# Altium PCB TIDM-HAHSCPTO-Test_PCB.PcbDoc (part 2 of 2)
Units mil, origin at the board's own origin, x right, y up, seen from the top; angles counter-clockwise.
Board outline 6700 x 4350 mil, 2 copper layers (Top Layer, Bottom Layer), stack 62 mil thick; 37 components, 162 nets, 491 pads, 55 vias.
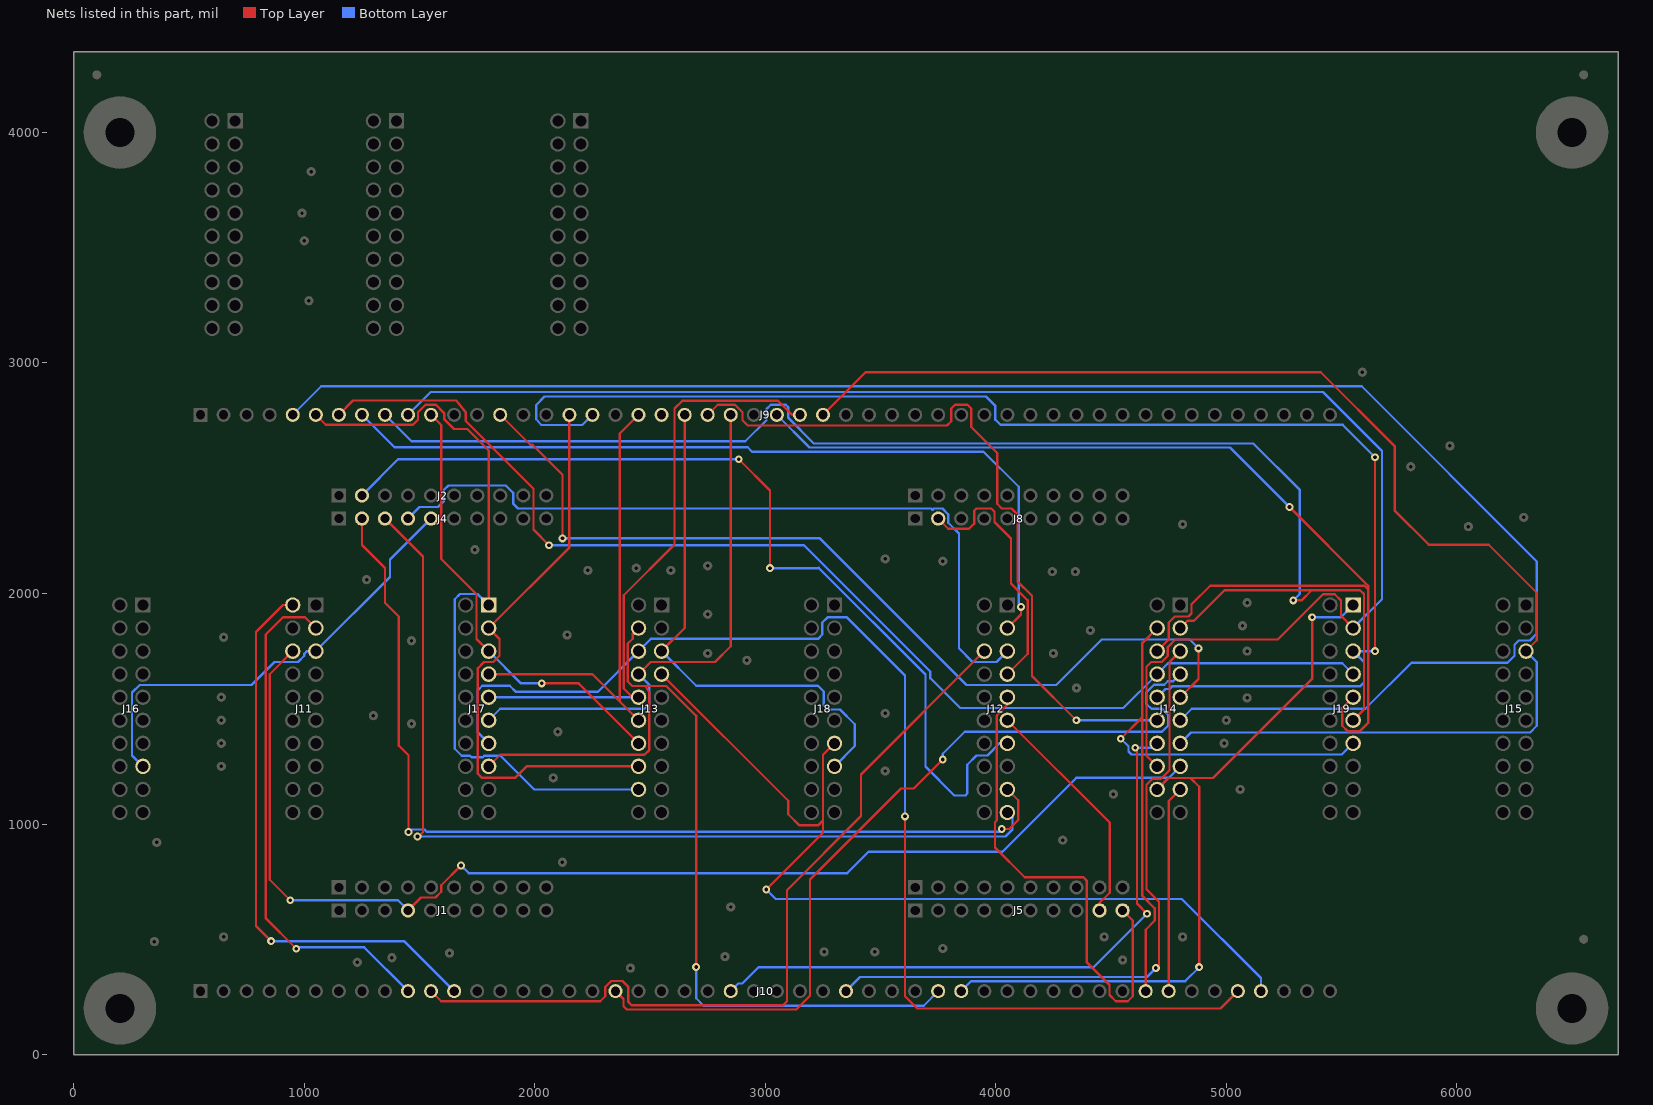
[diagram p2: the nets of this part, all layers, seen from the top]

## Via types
v1: diameter 34, hole 16, Top Layer to Bottom Layer, 55 vias

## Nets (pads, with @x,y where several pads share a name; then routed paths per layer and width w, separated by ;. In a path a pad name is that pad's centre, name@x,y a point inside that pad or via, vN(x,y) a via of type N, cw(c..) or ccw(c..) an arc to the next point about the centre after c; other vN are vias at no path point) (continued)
N2HET1_13/SCI3TX/N2HET2_20/EPWM5B: J1.4 J11.6 J14.15 | length 5341.1
  Top Layer w10: v1(939,669) 850.04,757.96 850.04,1650.04 J11.6@950,1750 ; J1.4@1450,625 1506,681 1569,681 1594,706 1594,734 v1(1680,820)
  Bottom Layer w10: v1(939,669) 1406,669 J1.4@1450,625 ; v1(1680,820) 1713,787 3355,787 3448,880 4029,880 4349,1200 4750,1200 J14.15@4800,1250
N2HET1_14: J4.5 J11.5 J16.15 | length 1997.8
  Bottom Layer w10: J16.15@300,1250 253,1297 253,1570 286,1603 771,1603 871,1703 973,1703 1000,1730 1000,1738 1012,1750 J11.5@1050,1750 1371.84,2071.84 1371.84,2146.84 J4.5@1550,2325
N2HET1_16/EPWM1SYNCI/EPWM1SYNCO: J4.3 J12.19 | length 4150.2
  Top Layer w10: J4.3@1350,2325 1515,2160 1515,964 1497,946 v1(1491,946)
  Bottom Layer w10: v1(1491,946) 4042,946 4072,976 4072,1050 J12.19@4050,1050
N2HET1_18/EMIF_RNW/EPWM6A: J4.2 J12.17 | length 4270.5
  Top Layer w10: J4.2@1250,2325 1250,2210 1350,2110 1350,1960 1410,1900 1410,1340 1452,1298 v1(1452,965) ; v1(4026,978) 4058,978 4097,1017 4097,1103 J12.17@4050,1150
  Bottom Layer w10: v1(1452,965) 1462.87,975.87 1521.05,975.87 1530.49,966.44 4014.44,966.44 v1(4026,978)
N2HET1_21/EMIF_NDQM_2: J10.24 J14.14 | length 2789.2
  Top Layer w10: v1(4605,1331) 4612,1324 4612,655 v1(4656,611)
  Bottom Layer w10: J10.24@2850,275 2883,308 2900,308 2971,379 4424,379 v1(4656,611) ; v1(4605,1331) 4681,1331 J14.14@4700,1350
N2HET1_22/EMIF_NDQM_3: J2.2 J12.13 | length 4067.6
  Top Layer w10: v1(2885,2582) 3020,2447 v1(3020,2110)
  Bottom Layer w10: J2.2@1250,2425 1407,2582 v1(2885,2582) ; v1(3020,2110) 3230.68,2110 3231.68,2111 3694.46,1648.22 3694.46,1249.54 3820,1124 3868,1124 3876,1132 3876,1257 3916,1297 3963.34,1297 4016.34,1350 J12.13@4050,1350
N2HET1_23/EMIF_BA_0: J10.12 J11.2 | length 2459.5
  Top Layer w10: v1(856,492) 790.76,557.24 790.76,1832.76 908,1950 J11.2@950,1950
  Bottom Layer w10: v1(856,492) 1433,492 J10.12@1650,275
N2HET1_24/MIBSPI1NCS_5/MII_RXD_0/RMII_RXD_0: J5.9 J12.11 | length 1027
  Top Layer w10: J12.11@4050,1450 4493.87,1006.13 4493.87,701.87 4450,658 J5.9@4450,625
N2HET1_26/MII_RXD_1/RMII_RXD_1: J5.10 J12.9 | length 2180.8
  Top Layer w10: J12.9@4050,1550 4050,1517 4003.66,1470.66 4003.66,1015.41 3996.13,1007.87 3996.13,897.87 4125,769 4380,769 4393.87,755.13 4393.87,401.13 4493.39,301.61 4493.39,258 4520.39,231 4572,231 4594,253 4594,581 J5.10@4550,625
N2HET1_27: J9.8 J12.3 | length 3619.8
  Top Layer w10: J12.3@4050,1850 4109,1909 v1(4109,1942)
  Bottom Layer w10: J9.8@1250,2775 1391,2634 2923.56,2634 2942.44,2615.13 3946.87,2615.13 4099,2463 4099,1952 v1(4109,1942)
N2HET1_28/MII_RXCLK/RMII_REFCLK/MII_RX_AVCLK4: J8.2 J12.7 | length 1139.1
  Top Layer w10: J8.2@3750,2325 3794,2281 3884,2281 3906.13,2303.13 3906.13,2359.13 3916,2369 3980,2369 3994,2355 3994,2310 4066,2238 4066,2042.87 4138.87,1970 4138.87,1738.87 J12.7@4050,1650
N2HET1_29: J10.11 J12.6 | length 3585
  Top Layer w10: J10.11@1550,275 1594,231 2284,231 2306,253 2306,293 2332,319 2380,319 2406,293 2406,228 2420.87,213.13 3076.13,213.13 3094,231 3094,713 3415.25,1034.25 3415.25,1215.25 J12.6@3950,1750
N2HET1_30/MII_RX_DV/EQEP2S: J4.4 J12.5 | length 3370.5
  Bottom Layer w10: J4.4@1450,2325 1500,2375 1580,2375 1606.13,2401.13 1606.13,2450 1625,2468.87 1874.13,2468.87 1906,2437 1906,2390 1927.13,2368.87 3718.8,2368.87 3724.42,2363.25 3726.2,2363.25 3731.83,2368.87 3768.17,2368.87 3793.87,2343.17 3793.87,2306.83 3840,2260.7 3840,1762 3899,1703 4003,1703 J12.5@4050,1750
N2HET1_31: J10.10 J11.3 | length 2251.8
  Top Layer w10: v1(965,459) 832.16,591.84 832.16,1821.16 908,1897 1003,1897 J11.3@1050,1850
  Bottom Layer w10: v1(965,459) 970.7,464.7 1260.3,464.7 J10.10@1450,275
N2HET2_0: J9.5 J14.11 | length 7807
  Bottom Layer w10: J9.5@950,2775 1074,2899 5587,2899 6347,2139 6347,1826 6317.34,1796.34 6268.34,1796.34 6250,1778 6250,1730 6220,1700 5803,1700 5603,1500 4850,1500 J14.11@4800,1450
N2HET2_1/N2HET1_NDIS: J9.6 J13.18 J17.1 | length 3291.5
  Top Layer w10: J9.6@1050,2775 1093.39,2731.61 1471,2731.61 1493.39,2754 1493.39,2786 1526.39,2819 1571,2819 1606.61,2783.39 1606.61,2757.03 1649.9,2713.74 1706.61,2713.74 1800,2620.35 J17.1@1800,1950
  Bottom Layer w10: J17.1@1800,1950 1752,1998 1676,1998 1653,1975 1653,1326 1682.66,1296.34 1719.19,1296.34 1725.53,1290 1774.47,1290 1780.81,1296.34 1851.61,1296.34 1997.95,1150 J13.18@2450,1150
N2HET2_2/N2HET2_NDIS: J9.18 J14.10 J19.5 | length 6148
  Top Layer w10: v1(5645,1750) v1(5645,2591)
  Bottom Layer w10: J9.18@2250,2775 2206,2731 2028,2731 2006,2756.25 2006,2818 2042.13,2854.13 3956.87,2854.13 3998,2813 3998,2754 4020.39,2731.61 5504.39,2731.61 v1(5645,2591) ; J14.10@4700,1550 4735.79,1585.79 4753,1585.79 4764.21,1597 5580,1597 5597,1614 5597,1703 J19.5@5550,1750 v1(5645,1750)
N2HET2_3/MIBSPI2CLK: J9.17 J13.16 J17.3 | length 2509
  Top Layer w10: J9.17@2150,2775 2150,2200 J17.3@1800,1850 1847,1803 1847,1730 1820,1703 1780,1703 1753,1676 1753,1218 1771,1200 1914,1200 1964,1250 J13.16@2450,1250
N2HET2_4: J9.14 J14.9 | length 4018.2
  Top Layer w10: J9.14@1850,2775 1980,2645 1990,2645 2120,2515 v1(2120,2239) ; J14.9@4800,1550 4879,1629 v1(4879,1762)
  Bottom Layer w10: v1(2120,2239) 3236.89,2239 3872.89,1603 4262,1603 4459,1800 4841,1800 v1(4879,1762)
N2HET2_5: J9.11 J13.14 J17.5 | length 1944.2
  Top Layer w10: J9.11@1550,2775 1593.87,2731.13 1593.87,2150.13 1747,1997 1747,1803 J17.5@1800,1750 ; v1(2030,1610) 2190,1610 2197,1603 J13.14@2450,1350
  Bottom Layer w10: J17.5@1800,1750 1940,1610 v1(2030,1610)
N2HET2_6: J9.7 J14.8 J19.7 | length 5224.5
  Top Layer w10: J9.7@1150,2775 1211.87,2836.87 1660,2836.87 1700,2787.39 1700,2748 1994,2454 1994,2277 v1(2061.87,2209.13)
  Bottom Layer w10: v1(2061.87,2209.13) 3167.5,2209.13 3716.14,1660.48 3716.14,1632 3845.15,1503 4553,1503 J14.8@4700,1650 4747,1697 5503,1697 J19.7@5550,1650
N2HET2_7/MIBSPI2NCS_0: J9.20 J13.12 J17.7 | length 2009.8
  Top Layer w10: J17.7@1800,1650 2250,1650 2367.91,1532.09 ; J13.12@2450,1450 2367.91,1532.09 ; J9.20@2450,2775 2367.91,2692.91 2367.91,1532.09
N2HET2_8: J10.19 J14.7 | length 3657.6
  Top Layer w10: J10.19@2350,275 2384.77,240.23 2384.77,209.77 2399.28,195.25 3134.25,195.25 3194,255 3194,759 3589,1154 3644,1154 v1(3770,1280)
  Bottom Layer w10: v1(3770,1280) 3770,1305 3865,1400 4721,1400 4747,1426 4747,1474 4721,1500 4675,1500 4653,1522 4653,1570 4686.66,1603.66 4730.66,1603.66 4746,1619 4769,1619 J14.7@4800,1650
N2HET2_9: J9.27 J13.10 J17.9 | length 2618.6
  Top Layer w10: J13.10@2450,1550 2424,1550 2385.79,1588.21 2385.79,1992.13 2606,2212.34 2606,2802 2640.26,2836.26 3054.74,2836.26 3116,2775 J9.27@3150,2775
  Bottom Layer w10: J17.9@1800,1550 J13.10@2450,1550
N2HET2_10: J9.26 J14.6 J19.9 | length 4853.5
  Top Layer w10: J14.6@4700,1750 4750,1800 4750,1874 4776,1900 4836,1900 4849,1913 4849,1953 4930,2034 5599,2034 5615,2018 ; v1(5274,2375) 5615,2034 5615,2018 ; J19.9@5550,1550 5503,1503 5503,1426 5526,1403 5580,1403 5615,1438 5615,2018
  Bottom Layer w10: J9.26@3050,2775 3192,2633 5016,2633 v1(5274,2375)
N2HET2_11: J9.24 J13.8 J17.11 | length 2329
  Top Layer w10: J13.8@2450,1650 2503,1703 2782,1703 2850,1771 J9.24@2850,2775
  Bottom Layer w10: J17.11@1800,1450 1850,1500 2476,1500 2497,1521 2497,1603 J13.8@2450,1650
N2HET2_12/MIBSPI2NENA/MIBSPI2NCS_1: J10.47 J13.7 J18.13 | length 4133.3
  Top Layer w10: J13.7@2550,1650 3099.53,1100.47 3099.53,1042.33 3147.86,994 3228,994 3250,1016 ; v1(3004,716) 3250,962 3250,1016 ; J18.13@3300,1350 3250,1300 3250,1016
  Bottom Layer w10: v1(3004,716) 3045,675 4806.62,675 5150,331.62 J10.47@5150,275
N2HET2_13/MIBSPI2SOMI: J10.46 J13.6 J17.13 | length 5279.6
  Top Layer w10: v1(3606,1033) 3606,253 3659,200 4975,200 J10.46@5050,275
  Bottom Layer w10: J17.13@1800,1350 1753,1397 1753,1581 1772,1600 1891.25,1600 1918.13,1573.13 2273.13,1573.13 J13.6@2450,1750 2503,1803 3228,1803 3247,1822 3247,1874 3269.34,1896.34 3354,1896.34 3606,1644.34 v1(3606,1033)
N2HET2_14/MIBSPI2SIMO: J9.22 J13.5 J18.15 | length 2289.9
  Top Layer w10: J13.5@2550,1750 2650,1850 J9.22@2650,2775
  Bottom Layer w10: J13.5@2550,1750 2700,1600 3228,1600 3253.66,1574.34 3253.66,1515.34 3272,1497 3324,1497 3388.21,1432.79 3388.21,1338.21 J18.15@3300,1250
N2HET2_15: J10.33 J13.4 J17.15 | length 3932.3
  Top Layer w10: J17.15@1800,1250 1850,1300 2476,1300 2497,1321 2497,1570 2480,1598.66 ; J13.4@2450,1850 2424.88,1824.88 2424.88,1803.66 2403.66,1782.44 2403.66,1618 2423,1598.66 2468.34,1598.66 2570.34,1598.66 2700,1469 v1(2700,380)
  Bottom Layer w10: v1(2700,380) 2700,244 2732,212 3687,212 J10.33@3750,275
N2HET2_16: J10.29 J14.5 | length 2870.4
  Top Layer w10: v1(4694.37,375.37) 4707.75,388.75 4707.75,662.75 4653.66,716.84 4653.66,1170 4680,1196.34 4716.34,1196.34 4753,1233 4753,1703 J14.5@4800,1750
  Bottom Layer w10: J10.29@3350,275 3411.26,336.26 4655.26,336.26 v1(4694.37,375.37)
N2HET2_17: J10.34 J14.18 J19.1 | length 3249.4
  Top Layer w10: J14.18@4700,1150 4749.19,1199.19 4844,1199.19 ; v1(4882,379) 4882,1161.19 4844,1199.19 ; v1(5372,1897) 5372,1629 4942.19,1199.19 4844,1199.19
  Bottom Layer w10: J10.34@3850,275 3893.39,318.39 4821.39,318.39 v1(4882,379) ; v1(5372,1897) 5497,1897 J19.1@5550,1950
N2HET2_18: J10.43 J14.17 | length 895.7
  Top Layer w10: J10.43@4750,275 4750,1100 J14.17@4800,1150
N2HET2_19/LIN2RX: J9.10 J14.16 J19.3 | length 6791.7
  Top Layer w10: J14.16@4700,1250 4653.66,1296.34 4653.66,1682 4674.66,1703 4719.34,1703 4746.34,1730 4746.34,1768 4778.34,1800 5223,1800 5419.34,1996.34 5470.66,1996.34 5497,1970 5497,1903 J19.3@5550,1850
  Bottom Layer w10: J9.10@1450,2775 1549,2874 5419,2874 5675,2618 5675,1975 J19.3@5550,1850
N2HET2_20/LIN2TX: J9.9 J14.3 J19.11 | length 6318.1
  Top Layer w10: J14.3@4800,1850 4831.78,1881.78 4859.3,1881.78 4991.73,2014.21 5370,2014.21 ; v1(5290,1970) 5325.79,1970 5370,2014.21 ; J19.11@5550,1450 5597,1497 5597,1997.21 5580,2014.21 5370,2014.21
  Bottom Layer w10: J9.9@1350,2775 1465,2660 2913,2660 3005,2752 3005,2800 3023.39,2818.39 3088.61,2818.39 3100,2807 3100,2761.41 3210.54,2650.87 5117.13,2650.87 5319,2449 5319,1999 v1(5290,1970)
N2HET2_21: J10.42 J14.4 J19.13 | length 2855.8
  Top Layer w10: v1(4542.12,1370.13) 4632,1460 4635.79,1460 ; J10.42@4650,275 4650,541.13 4689.87,581 4689.87,634 4635.79,688.09 4635.79,1460 ; J14.4@4700,1850 4635.79,1785.79 4635.79,1460
  Bottom Layer w10: v1@4530,1370 v1@4540,1380 ; v1(4542.12,1370.13) 4575.13,1337.12 4575.13,1313.97 4588,1301.1 5501.1,1301.1 J19.13@5550,1350
N2HET2_22: J9.28 J14.13 J15.5 | length 5928.5
  Top Layer w10: J9.28@3250,2775 3435,2960 5410,2960 5730,2640 5730,2360 5878.69,2211.32 6138.69,2211.32 6347,2003 6347,1797 J15.5@6300,1750
  Bottom Layer w10: J14.13@4800,1350 4847,1397 6318,1397 6347,1426 6347,1703 J15.5@6300,1750
N2HET2_23: J9.23 J14.12 | length 3210.2
  Top Layer w10: J9.23@2750,2775 2793.39,2818.39 2868.61,2818.39 2901,2786 2901,2752 2924,2729 3788,2729 3806.61,2747.61 3806.61,2802 3823,2818.39 3877,2818.39 3893.39,2802 3893.39,2722 4006,2609.39 4006,2389 4026,2369 4068.05,2369 4094.04,2343.01 4094.04,2052.46 4156.75,1989.75 4156.75,1642.47 v1(4349.21,1450)
  Bottom Layer w10: v1(4349.21,1450) J14.12@4700,1450
NERROR: J9.21
pads on no net: FID1.1 FID2.1 FID3.1 H1.1 H2.1 H3.1 H4.1 J3.9 J3.10 J7.9 J7.10 J10.8 J10.9 J10.48 J10.49 J10.50 J11.1 J11.4 J11.8 J12.1 J12.4 J12.15 J13.1 J13.2 J13.3 J14.1 J14.2 J15.7 J15.9 J15.11 J15.13 J15.15 J15.17 J15.19 J16.17 J16.19 J17.17 J17.19 J18.17 J18.19 J19.15 J19.17 J19.19 J20.1 J20.2 J20.3 J21.17 J21.19 J22.17 J22.19

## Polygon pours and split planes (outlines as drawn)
GND on Bottom Layer "BOTTOM_LAYER_GND_P002" (solid, remove dead copper, pour order 2): 101.17,399.51 401.17,399.51 401.17,99.51 6301.17,99.51 6301.17,399.51 6601.17,399.51 6601.17,3799.51 6301.17,3799.51 6301.17,4199.51 401.17,4199.51 401.17,3799.51 101.17,3799.51
GND on Top Layer "TOP_LAYER_GND_P000" (solid, remove dead copper, pour order 0): 100,400 400,400 400,100 6300,100 6300,400 6600,400 6600,3800 6300,3800 6300,4200 400,4200 400,3800 100,3800

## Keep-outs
Keep-Out Layer:
  text ".Layer_Name" at 577,-858.49 h60

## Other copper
Top Layer:
  text ".Layer_Name" at 577,-858.49 h60
Bottom Layer:
  text ".Layer_Name" at 577,-858.49 h60

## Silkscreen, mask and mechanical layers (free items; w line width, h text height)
Top Overlay:
  region: 6200,3590 5900,3590 5900,3490 6200,3490
  text "'.PRJ_Number'.PCB_Rev-" at 4970,3500 h108.27
  text ".Layer_Name" at 577,-858.49 h60
Bottom Overlay:
  text ".Layer_Name" at 577,-858.49 h60
Top Paste:
  text ".Layer_Name" at 577,-858.49 h60
Bottom Paste:
  text ".Layer_Name" at 577,-858.49 h60
Top Solder:
  text ".Layer_Name" at 577,-858.49 h60
  text ".Layer_Name" at 577,-858.49 h60
Bottom Solder:
  text ".Layer_Name" at 577,-858.49 h60
Drill Guide:
  text ".Layer_Name" at 577,-858.49 h60
M1 Board Outline:
  the board outline again, w10
  text ".Layer_Name" at 577,-858.49 h60
M2 Board Dimensions:
  rectangle: 0,-275 125,-150
  rectangle: 125,-400 500,-275
  lines w7: 0,-275 1000,-275 ; 125,-400 125,-150 ; 250,-400 250,-150 ; 500,-400 500,-150 ; 750,-400 750,-150 ; 0,-400 1000,-400 1000,-150 0,-150 0,-400
  text ".Layer_Name" at 577,-858.49 h60
M3 3D STEP Top:
  text ".Layer_Name" at 577,-858.49 h60
M4 3D STEP Bottom:
  text ".Layer_Name" at 577,-858.49 h60
M5 Assembly Top:
  lines w10: -292,-930.17 6308,-930.17 ; -292,-726.83 6310,-726.83 ; -292,-523.5 -292,-1133.5 3713,-1133.5 6310,-1133.5 6310,-523.5 -291.5,-523.5 -291.5,-1133.5 1284,-1133.5 ; 2173,-1133.5 2173,-523.5 ; 3440,-726.83 3440,-523.5 ; 4280,-726.83 4280,-523.5 ; 4902,-1140 4902,-937.17
  text "COMPONENTS MARKED 'DNP' SHOULD NOT BE POPULATED." at 1153.5,-318.5 h60
  text "ASSEMBLY VARIANT:" at 1153,-434 h60
  text ".VariantName" at 2189,-434 h60
  text "PCB VIEWED FROM TOP SIDE" at -228.5,-655.67 h60
  text "BOARD #:" at 2248,-655.67 h60
  text ".PRJ_Number" at 2793.5,-655.67 h60
  text "REV:" at 3638,-655.67 h60
  text ".PCB_Rev" at 3929.5,-655.67 h60
  text "SVN REV:" at 4476,-655.67 h60
  text ".VersionControl_RevNumber" at 4982,-655.67 h60
  text "TID #:" at 2248,-859 h60
  text ".TID" at 2793.5,-859 h60
  text "PLOT NAME =" at -228.5,-1064.34 h60
  text ".plot_File_Name" at 577,-1064.34 h60
  text "GENERATED    :" at 2250,-1064.34 h60
  text ".Print_Date" at 3119.5,-1064.34 h60
  text ".Print_Time" at 3848.5,-1064.34 h60
  text "TEXAS INSTRUMENTS" at 5113,-1064.34 h60
M6 Assembly Bottom:
  lines w10: -292.5,-727.33 6309.5,-727.33 ; -290.5,-930.67 6309.5,-930.67 ; 1115.5,-1140.5 1115.5,-937.67 ; 1737.5,-727.33 1737.5,-524 ; 2577.5,-727.33 2577.5,-524 ; 3844.5,-1134 3844.5,-524 ; 4733.5,-1134 6309,-1134 6309,-524 -292.5,-524 -292.5,-1134 2304.5,-1134 6309.5,-1134 6309.5,-524
  text "COMPONENTS MARKED 'DNP' SHOULD NOT BE POPULATED." at 6102,-318 h60
  text ".VariantName" at 5058,-434 h60
  text "ASSEMBLY VARIANT:" at 6097,-434 h60
  text ".VersionControl_RevNumber" at 1035.5,-656.17 h60
  text "SVN REV:" at 1541.5,-656.17 h60
  text ".PCB_Rev" at 2088,-656.17 h60
  text "REV:" at 2379.5,-656.17 h60
  text ".PRJ_Number" at 3224,-656.17 h60
  text "BOARD #:" at 3769.5,-656.17 h60
  text "PCB VIEWED FROM BOTTOM SIDE" at 6246,-656.17 h60
  text ".TID" at 3224,-859.5 h60
  text "TID #:" at 3769.5,-859.5 h60
  text "TEXAS INSTRUMENTS" at 904.5,-1064.84 h60
  text ".Print_Time" at 2169,-1064.84 h60
  text ".Print_Date" at 2898,-1064.84 h60
  text "GENERATED    :" at 3767.5,-1064.84 h60
  text ".plot_File_Name" at 5440.5,-1064.84 h60
  text "PLOT NAME =" at 6246,-1064.84 h60
M9 Title Sheet:
  drawing of 57 lines, arcs and shapes, not listed
  text "1" at 739.84,8036.5 h70
  text "2" at 3235.5,8036.5 h70
  text "3" at 5724.84,8036.5 h70
  text "4" at 8231.51,8036.5 h70
  text "5" at 10730.5,8036.5 h70
  text "6" at 13235.5,8036.5 h70
  text "A" at -416.5,6893.5 h70
  text "A" at 14383.5,6893.5 h70
  text "B" at -416.5,4513.5 h70
  text "B" at 14383.5,4513.5 h70
  text "C" at -416.5,2138.5 h70
  text "C" at 14383.5,2138.5 h70
  text "PROJECT TITLE:" at 11343.5,277.5 h45
  text ".PRJ_Title" at 11393.5,144.17 h70
  text "DESIGNED FOR:" at 11343.5,-23.5 h45
  text ".PRJ_Customer" at 11393.5,-163.5 h70
  text "D" at -416.5,-231.5 h70
  text "D" at 14383.5,-231.5 h70
  text "FILE NAME:" at 11343.5,-323.5 h45
  text ".PCB_File_Name_No_Path" at 11393.5,-443.5 h70
  text "Texas Instruments (TI) and/or its licensors do not warrant the accuracy or completeness of this specification" at 6374,-605.34 h45
  text "ENGINEER:" at 11343.5,-613.5 h45
  text "LAYOUT BY:" at 12848.5,-613.5 h45
  text "or any information contained therein. TI and/or its licensors do not warrant that this design will meet" at 6329.01,-718 h45
  text ".PRJ_Engineer" at 11393.5,-768.49 h70
  text ".PCB_Layout" at 12899,-768.49 h70
  text "the specifications, will be suitable for your application or fit for any particular purpose, or will operate in" at 6329.01,-830.67 h45
  text ".Layer_Name" at 577,-858.49 h60
  text "ALTIUM DESIGNER VERSION:" at 12848.5,-923.5 h45
  text "an implementation. TI and/or its licensors do not warrant that the design is production worthy. You should" at 6329.01,-943.33 h45
  text "completely validate and test your design implementation to confirm the system functionality for your application." at 6374,-1056 h45
  text ".print_Scale" at 11393.5,-1056.83 h70
  text ".Application_BuildNumber" at 12899,-1056.83 h70
  text "1" at 739.84,-1263.5 h70
  text "2" at 3235.5,-1263.5 h70
  text "3" at 5724.84,-1263.5 h70
  text "4" at 8231.51,-1263.5 h70
  text "5" at 10730.5,-1263.5 h70
  text "6" at 13235.5,-1263.5 h70
M10 Fab Notes:
  drawing of 173 lines, arcs and shapes, not listed
  text "DESIGN INFORMATION" at 12378.02,6201 h60
  text "MIN. TRACK WIDTH:" at 11733.46,6021 h60
  text "8" at 12829.7,6021 h60
  text "MIL" at 12984.46,6021 h60
  text "MIN. CLEARANCE:" at 11733.46,5889 h60
  text "0.2" at 12769.7,5889 h60
  text "mm" at 12984.46,5889 h60
  text "MIN. VIA PAD SIZE:" at 11733.46,5757 h60
  text "24" at 12799.71,5757 h60
  text "MIL" at 12984.46,5757 h60
  text "0.05mm (2MIL)" at 12428.46,5615.29 h60
  text "MINIMUM ANNULAR RING" at 11404.23,5611 h60
  text "EXTERNAL" at 13136.46,5611 h60
  text "PER" at 11604.23,5493 h60
  text "IPC-D-275 CLASS 2 LEVEL C" at 11824.23,5493 h60
  text "MIL, HOLES" at 13312.46,5380.71 h60
  text "+/-" at 12920,5380 h60
  text "+/-" at 13774,5380 h60
  text "REGISTRATION TOLERANCES:" at 11404.23,5375 h60
  text "METAL" at 12604,5375 h60
  text "5" at 13180.2,5375 h60
  text "3" at 14013.2,5375 h60
  text "MIL" at 14129.46,5375 h60
  text "+/-" at 13774,5262 h60
  text "HOLE SIZE TOLERANCE (UNLESS OTHERWISE SPECIFIED):" at 11404.23,5257 h60
  text "3" at 14013.2,5257 h60
  text "MIL" at 14129.46,5257 h60
  text "MATERIAL:" at 11329.46,5047.54 h60
  text "FR-4 High Tg" at 12315.9,4907.21 h60
  text "FR-408" at 11750.46,4898.64 h60
  text "OTHER" at 13238.46,4898.64 h60
  text "X" at 12161,4895 h60
  text "62 MIL (1.6mm) +/-10%" at 12070.56,4735.92 h60
  text "THICKNESS:" at 11404.23,4731.64 h60
  text "X" at 11942.4,4731.64 h60
  text "OTHER" at 13355.46,4731.64 h60
  text "TOLERANCE:" at 11404.23,4573.64 h60
  text "X" at 12243.53,4573.64 h60
  text "ANSI IPC-6012 TYPE 3 CLASS 2" at 12430.48,4573.64 h60
  text "OTHER +/-" at 12430.46,4417.64 h60
  text "BOW & TWIST:" at 11404.23,4260.64 h60
  text "X" at 12243.53,4260.64 h60
  text "ANSI IPC-6012 TYPE 3 CLASS 2" at 12430.48,4260.64 h60
  text "OTHER +/-" at 12430.46,4102.13 h60
  text "DRILLING:" at 11329.46,3963.64 h60
  text "REFERENCE:" at 11404.23,3846.64 h60
  text "X" at 12052.46,3846.64 h60
  text "AS SHOWN" at 12239.46,3846.64 h60
  text "X" at 12953.46,3846.64 h60
  text "NC_DRILL FILES" at 13090.46,3846.64 h60
  text "PTH COPPER THICKNESS:" at 11404.23,3688.64 h60
  text "X" at 12534.46,3688.64 h60
  text "20-30 um" at 12671.46,3688.64 h60
  text "OTHER" at 13388.46,3688.64 h60
  text "BOARD FINISH:" at 11329.46,3529.64 h60
  text "SILKSCREEN:" at 11484.68,3411.64 h60
  text "X" at 12433.46,3411.64 h60
  text "TOP" at 12559.46,3411.64 h60
  text "X" at 12943.46,3411.64 h60
  text "BOTTOM" at 13070.46,3411.64 h60
  text "SILKSCREEN COLOR:" at 11484.68,3244.64 h60
  text "X" at 12432.42,3244.64 h60
  text "WHITE" at 12559.46,3244.64 h60
  text "OTHER" at 13070.46,3244.64 h60
  text "X" at 12563.42,3085.44 h60
  text "GREEN" at 12690.46,3085.44 h60
  text "OTHER" at 13308.46,3085.44 h60
  text "SOLDER RESIST COLOR:" at 11484.68,3074.64 h60
  text "X" at 12563.42,2915.44 h60
  text "MATTE" at 12690.46,2915.44 h60
  text "SEMI-GLOSS" at 13308,2914.8 h60
  text "IMMERSION GOLD (ENIG)" at 12390.46,2726.92 h60
  text "ENEPIG" at 13728,2723.64 h60
  text "SURFACE FINISH:" at 11329.46,2722.64 h60
  text "X" at 12203.51,2722.64 h60
  text "IMM. TIN/SILVER OR EQUIV" at 11659,2565.64 h60
  text "OTHER" at 13090.46,2565.64 h60
  text "ARRAY/PANEL:" at 11329.46,2386.64 h60
  text "CUT AND TRIM PER M1 BOARD OUTLINE" at 12390.46,2382.35 h60
  text "N.C. ROUTE" at 12390.46,2230.64 h60
  text "X" at 13069.46,2230.64 h60
  text "V. SCORE" at 13256.46,2230.64 h60
  text "CERTIFICATION:" at 11329.46,2093.64 h60
  text "MATERIALS AND WORKMANSHIP FOR ALL PCBS" at 12054.46,2093.64 h60
  text "TO MEET OR EXCEED THE REQUIREMENTS OF:" at 12054.46,1995.64 h60
  text "X" at 11680.96,1859.13 h60
  text "ANSI IPC-A-600F CLASS ->" at 11819.96,1859.13 h60
  text "X" at 13459.02,1859.13 h60
  text "2" at 13577.96,1859.14 h60
  text "1" at 13262.96,1857.64 h60
  text "3" at 13931.96,1857.64 h60
  text "X" at 12495.02,1699.64 h60
  text "RoHS" at 12631.96,1699.64 h60
  text "OTHER" at 13276.36,1699.64 h60
  text "PER ORDER" at 13673.42,1699.64 h60
  text "ALL BOARDS MUST MEET OR EXCEED UL94-V0 REQUIREMENTS." at 11357,1534 h60
  text "PCB MUST BEAR THE UL94V-0 UL REGISTERED MATERIAL ID NUMBER" at 11357,1414 h60
  text "ADDITIONAL REQUIREMENTS:" at 11329.46,1240.64 h60
  text "MICROSECTION:" at 11404.23,1125.64 h60
  text "YES" at 12309.96,1125.64 h60
  text "REQUIRED" at 13171.46,969.49 h60
  text "BARE BOARD ELEC. TEST:" at 11404.23,966.64 h60
  text "NONE" at 12709.96,966.64 h60
  text "X" at 13044.46,966.64 h60
  text "PER ORDER" at 13763.46,966.64 h60
  text ".Layer_Name" at 577,-858.49 h60
M11 Gerber Information:
  lines w10: -292,-930.17 6308,-930.17 ; -292,-726.83 6310,-726.83 ; -292,-523.5 -292,-1133.5 3713,-1133.5 6310,-1133.5 6310,-523.5 -291.5,-523.5 -291.5,-1133.5 1284,-1133.5 ; 2173,-1133.5 2173,-523.5 ; 3440,-726.83 3440,-523.5 ; 4280,-726.83 4280,-523.5 ; 4902,-1140 4902,-937.17
  text "ALL ARTWORK VIEWED FROM TOP SIDE" at -228.5,-655.67 h60
  text "BOARD #:" at 2248,-655.67 h60
  text ".PRJ_Number" at 2793.5,-655.67 h60
  text "REV:" at 3638,-655.67 h60
  text ".PCB_Rev" at 3929.5,-655.67 h60
  text "SVN REV:" at 4476,-655.67 h60
  text ".VersionControl_RevNumber" at 4982,-655.67 h60
  text "LAYER NAME =" at -228.5,-858.49 h60
  text "TID #:" at 2248,-859 h60
  text ".TID" at 2793.5,-859 h60
  text "PLOT NAME =" at -228.5,-1064.34 h60
  text ".plot_File_Name" at 577,-1064.34 h60
  text "GENERATED    :" at 2250,-1064.34 h60
  text ".Print_Date" at 3119.5,-1064.34 h60
  text ".Print_Time" at 3848.5,-1064.34 h60
  text "TEXAS INSTRUMENTS" at 5113,-1064.34 h60
M12 Stackup:
  drawing of 191 lines, arcs and shapes, not listed
  text "Layer" at 9790.34,7830 h60
  text "Name" at 10200.26,7830 h60
  text "Material" at 11130,7830 h60
  text "Thickness" at 11989.77,7830 h60
  text "Constant" at 12639.6,7830 h60
  text "Board Layer Stack" at 13209.46,7830 h60
  text "1" at 9790.34,7710 h60
  text "Top Overlay" at 10200.26,7710 h60
  text "2" at 9790.34,7590 h60
  text "Top Solder" at 10200.26,7590 h60
  text "Solder Resist" at 11130,7590 h60
  text "0.40mil" at 11989.77,7590 h60
  text "3.5" at 12639.6,7590 h60
  text "3" at 9790.34,7470 h60
  text "Top Layer" at 10200.26,7470 h60
  text "Copper" at 11130,7470 h60
  text "1.40mil" at 11989.77,7470 h60
  text "4" at 9790.34,7350 h60
  text "Dielectric1" at 10200.26,7350 h60
  text "FR-4" at 11130,7350 h60
  text "59.20mil" at 11989.77,7350 h60
  text "4.8" at 12639.6,7350 h60
  text "5" at 9790.34,7230 h60
  text "Bottom Layer" at 10200.26,7230 h60
  text "Copper" at 11130,7230 h60
  text "1.40mil" at 11989.77,7230 h60
  text "6" at 9790.34,7110 h60
  text "Bottom Solder" at 10200.26,7110 h60
  text "Solder Resist" at 11130,7110 h60
  text "0.40mil" at 11989.77,7110 h60
  text "3.5" at 12639.6,7110 h60
  text "7" at 9790.34,6990 h60
  text "Bottom Overlay" at 10200.26,6990 h60
  text ".Layer_Name" at 577,-858.49 h60
M13 Component Bodies Top:
  text ".Layer_Name" at 577,-858.49 h60
M14 Component Bodies Bottom:
  text ".Layer_Name" at 577,-858.49 h60
M15 Courtyards Top:
  text ".Layer_Name" at 577,-858.49 h60
M16 Courtyards Bottom:
  text ".Layer_Name" at 577,-858.49 h60
Drill Drawing:
  circle w10: c7234.85,3462.03 r27.63
  lines w10: 7207.23,3613.97 7262.48,3613.97 7234.85,3558.72 7207.23,3613.97 ; 7207.23,3683.04 7262.48,3683.04 7262.48,3738.29 7207.23,3738.29 7207.23,3683.04 ; 7207.23,3821.17 7221.04,3821.17 7234.85,3807.36 7248.67,3821.17 7262.48,3821.17 7248.67,3834.99 7262.48,3848.8 7248.67,3848.8 7234.85,3862.61 7221.04,3848.8 7207.23,3848.8 7221.04,3834.99 7207.23,3821.17 ; 7207.23,3931.68 7234.85,3945.49 7262.48,3931.68 7248.67,3959.31 7262.48,3986.93 7234.85,3973.12 7207.23,3986.93 7221.04,3959.31 7207.23,3931.68 ; 7207.23,4069.81 7221.04,4069.81 7221.04,4056 7248.67,4056 7248.67,4069.81 7262.48,4069.81 7262.48,4097.44 7248.67,4097.44 7248.67,4111.25 7221.04,4111.25 7221.04,4097.44 7207.23,4097.44 7207.23,4069.81
  lines w12: 7157.14,3397.1 10388.63,3397.1 ; 7157.14,4143.02 10388.63,4143.02 ; 7495,3272.78 7495,4267.34 ; 7827,3272.78 7827,4267.34 ; 8463.56,3272.78 8463.56,4267.34 ; 8722.7,3272.78 8722.7,4267.34 ; 9097.86,3272.78 9097.86,4267.34 ; 9822.19,3272.78 9822.19,4267.34 ; 7157.14,3272.78 10388.63,3272.78 10388.63,4267.34 7157.14,4267.34 7157.14,3272.78
  text "Symbol" at 7231.73,4180.32 h72
  text "Quantity" at 7532.3,4180.32 h72
  text "Finished Hole Size" at 7864.3,4180.32 h72
  text "Plated" at 8500.86,4180.32 h72
  text "Hole Type" at 8760,4180.32 h72
  text "Drill Layer Pair" at 9135.16,4180.32 h72
  text "Hole Tolerance" at 9859.49,4180.32 h72
  text "64" at 7532.3,4056 h60
  text "15.00mil (0.381mm)" at 7864.3,4056 h60
  text "PTH" at 8500.86,4056 h60
  text "Round" at 8760,4056 h60
  text "Top Layer - Bottom Layer" at 9135.16,4056 h60
  text "55" at 7532.3,3931.68 h60
  text "16.00mil (0.406mm)" at 7864.3,3931.68 h60
  text "PTH" at 8500.86,3931.68 h60
  text "Round" at 8760,3931.68 h60
  text "Top Layer - Bottom Layer" at 9135.16,3931.68 h60
  text "8" at 7532.3,3807.36 h60
  text "40.00mil (1.016mm)" at 7864.3,3807.36 h60
  text "PTH" at 8500.86,3807.36 h60
  text "Round" at 8760,3807.36 h60
  text "Top Layer - Bottom Layer" at 9135.16,3807.36 h60
  text "172" at 7532.3,3683.04 h60
  text "40.16mil (1.020mm)" at 7864.3,3683.04 h60
  text "PTH" at 8500.86,3683.04 h60
  text "Round" at 8760,3683.04 h60
  text "Top Layer - Bottom Layer" at 9135.16,3683.04 h60
  text "240" at 7532.3,3558.72 h60
  text "47.24mil (1.200mm)" at 7864.3,3558.72 h60
  text "PTH" at 8500.86,3558.72 h60
  text "Round" at 8760,3558.72 h60
  text "Top Layer - Bottom Layer" at 9135.16,3558.72 h60
  text "4" at 7532.3,3434.4 h60
  text "125.98mil (3.200mm)" at 7864.3,3434.4 h60
  text "PTH" at 8500.86,3434.4 h60
  text "Round" at 8760,3434.4 h60
  text "Top Layer - Bottom Layer" at 9135.16,3434.4 h60
  text "543 Total" at 7532.3,3310.08 h60
  text ".Layer_Name" at 577,-858.49 h60
M17 Embedded Cavity:
  text ".Layer_Name" at 577,-858.49 h60
M18 Embedded Assembly:
  text ".Layer_Name" at 577,-858.49 h60
M19 Embedded Keepout:
  text ".Layer_Name" at 577,-858.49 h60

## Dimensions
0,-400 to 1000,-400 on M2 Board Dimensions
0,0 to 0,4350 on M2 Board Dimensions
0,0 to 6700,0 on M2 Board Dimensions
